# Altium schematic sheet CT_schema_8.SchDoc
size 147 x 119 mm
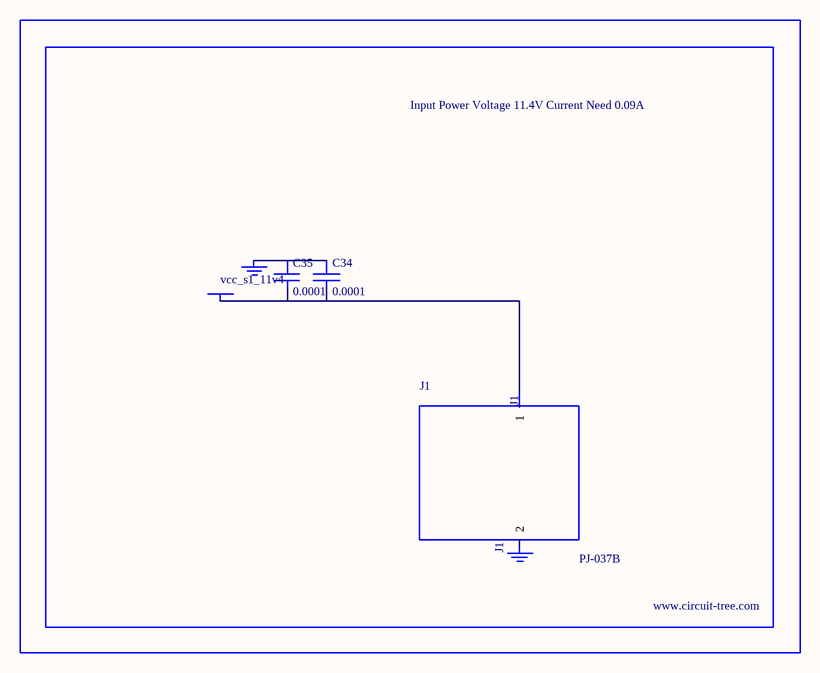
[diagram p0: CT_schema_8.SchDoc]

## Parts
BORDER7  (no value)
C34  0.0001  [EXV-9H]
C35  0.0001  [EXV-9H]
GND_INSTANCE_7_0  (no value)
GND_INSTANCE_7_1  (no value)
J1  PJ-037B  [PJ-037B_PACKAGE]
POWER_INSTANCE_7_0  vcc_s1_11v4

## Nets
NetC34_1: C34.1 C35.1 GND_INSTANCE_7_0.0(GND)
NetC34_2: C34.2 C35.2 J1.1 POWER_INSTANCE_7_0.0(PWR)

Not connected (* = marked no-connect by the designer): GND_INSTANCE_7_1 0(GND); J1 2

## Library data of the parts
BORDER7 = BORDER_PAGE7
C34 C35 = EDK107M035A9HAA
GND_INSTANCE_7_0 GND_INSTANCE_7_1 = GND
POWER_INSTANCE_7_0 = PWR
